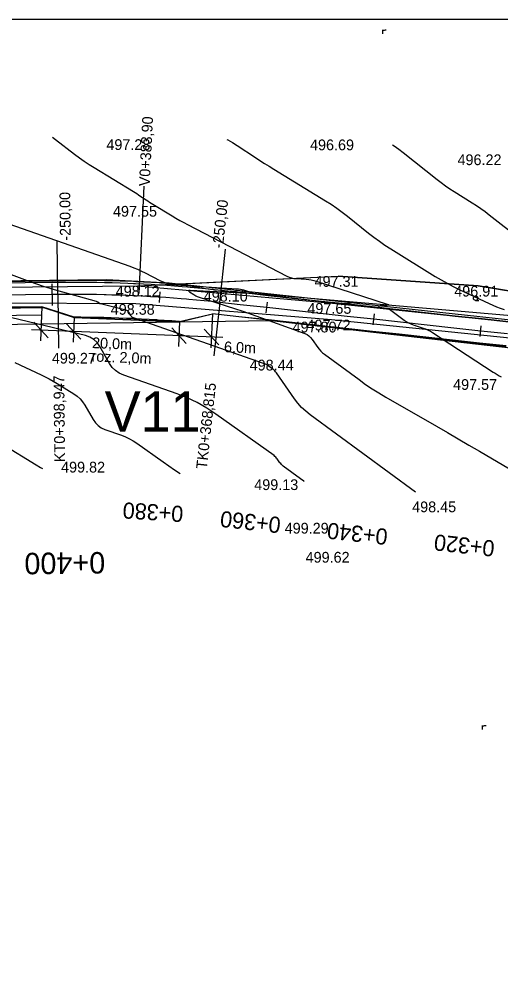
# Model space of a CAD drawing. Extents: x -636600 to -628587, y -1090963 to -1085869.
# Drawn here: x -629421.1 to -629331.5, y -1089367.8 to -1089190 of the extents above; entities that cross this region are included whole.
import ezdxf

# ---------------------------------------------------------------- set-up
doc = ezdxf.new("R2010")
doc.units = 0
for name, color, linetype in [('01_PARCELY_NÁVRH_PC', 7, 'Continuous'), ('03_PC_OBJEKTY_NÁVRH', 7, 'Continuous'), ('06_ÚSES_IP_NAVRH', 7, 'Continuous'), ('08_LEGENDA_HV', 7, 'Continuous'), ('40', 7, 'Continuous'), ('42', 7, 'Continuous'), ('43', 7, 'Continuous'), ('55', 7, 'Continuous'), ('Ex_Major Contours', 7, 'Continuous'), ('Ex_Minor Contours', 7, 'Continuous'), ('HEKTOMETRY100', 7, 'Continuous'), ('HEKTOMETRY20', 7, 'Continuous'), ('HL_BODY', 7, 'Continuous'), ('koty_vše', 7, 'Continuous'), ('POLOMERY', 7, 'Continuous'), ('popis', 7, 'Continuous'), ('situace_osa', 7, 'Continuous'), ('situace_těleso', 7, 'Continuous'), ('situace_vozovka', 7, 'Continuous'), ('VRCHOLY', 7, 'Continuous')]:
    doc.layers.add(name, color=color, linetype=linetype)

msp = doc.modelspace()

# ---------------------------------------------------------------- linework, layer by layer
at = {"layer": '01_PARCELY_NÁVRH_PC'}
for points in [[(-629219.96, -1089257.88), (-629393.2, -1089239.09), (-629404.84, -1089238.49), (-629532.17, -1089240), (-629618.76, -1089242.62), (-629630.23, -1089244.94), (-629692.43, -1089269.15), (-629702.88, -1089275.33), (-629709.57, -1089280.47), (-629719.03, -1089292.94), (-629735.64, -1089330.23), (-629741.78, -1089338.98), (-629748.13, -1089344.96), (-629754.15, -1089347.42), (-629771.79, -1089346.48), (-629796.88, -1089348.54), (-629815.64, -1089354.58), (-629845.21, -1089367.17), (-629847.27, -1089367.82)], [(-629544.07, -1089245.47), (-629416.57, -1089243.64), (-629410.87, -1089245.47), (-629391.26, -1089246.28), (-629374.19, -1089246.04), (-629308.62, -1089253.58)]]:
    msp.add_lwpolyline(points, dxfattribs=at)
for points in [[(-629393.2, -1089239.09), (-629390.9, -1089239.21), (-629361.77, -1089237.78), (-629335.73, -1089239.6), (-629294.48, -1089246.34), (-629131.6, -1089265), (-629137.99, -1089267.3), (-629219.96, -1089257.88)], [(-629391.26, -1089246.28), (-629410.87, -1089245.47), (-629416.57, -1089243.64), (-629544.07, -1089245.47), (-629606.23, -1089247.86), (-629622.77, -1089249.5), (-629631.42, -1089251.64), (-629681.41, -1089270.27), (-629685.4, -1089272.16), (-629664.77, -1089267.27), (-629630.53, -1089254.51), (-629622.26, -1089252.46), (-629606.02, -1089250.85), (-629543.99, -1089248.47), (-629417.02, -1089246.65)]]:
    msp.add_lwpolyline(points, close=True, dxfattribs=at)
at = {"layer": '06_ÚSES_IP_NAVRH'}
msp.add_lwpolyline([(-629416.96, -1089245.08), (-629541.78, -1089246.72), (-629627.12, -1089251.56), (-629664.34, -1089265.4)], dxfattribs=at)
at = {"layer": '08_LEGENDA_HV'}
msp.add_line((-629847.27, -1089189.97), (-629007.27, -1089189.97), dxfattribs=at)
at = {"layer": '40'}
for p, q in [((-629450.76, -1089240.14), (-629399.07, -1089239.61)), ((-629399.07, -1089239.61), (-629362.81, -1089242.8)), ((-629399.42, -1089242.98), (-629450.87, -1089242.7)), ((-629363.01, -1089245.9), (-629399.42, -1089242.98)), ((-629362.81, -1089242.8), (-629311.2, -1089248.31)), ((-629311.6, -1089251.23), (-629363.01, -1089245.9))]:
    msp.add_line(p, q, dxfattribs=at)
at = {"layer": '42'}
for p, q in [((-629399.07, -1089239.61), (-629361.77, -1089237.78)), ((-629335.73, -1089239.6), (-629361.77, -1089237.78)), ((-629311.31, -1089243.59), (-629335.73, -1089239.6))]:
    msp.add_line(p, q, dxfattribs=at)
at = {"layer": '43'}
for p, q in [((-629336.25, -1089242.31), (-629336.15, -1089242.31)), ((-629336.15, -1089242.31), (-629335.65, -1089242.31))]:
    msp.add_line(p, q, dxfattribs=at)
for points in [[(-629353.51, -1089192.7), (-629353.51, -1089191.97)], [(-629353.51, -1089192.21), (-629353.41, -1089192.11), (-629353.31, -1089192.05), (-629353.15, -1089192), (-629353, -1089191.98), (-629352.84, -1089191.97)], [(-629334.95, -1089322.13), (-629334.95, -1089321.4)], [(-629334.95, -1089321.63), (-629334.85, -1089321.54), (-629334.75, -1089321.47), (-629334.59, -1089321.43), (-629334.44, -1089321.4), (-629334.29, -1089321.4)]]:
    msp.add_lwpolyline(points, dxfattribs=at)
msp.add_circle((-629336.25, -1089241.91), 0.4, dxfattribs=at)
msp.add_arc((-629336.15, -1089241.91), 0.4, 259.6952, 97.1808, dxfattribs=at)
at = {"layer": '55'}
msp.add_line((-629382.61, -1089240.52), (-629320.04, -1089245.98), dxfattribs=at)
at = {"layer": 'Ex_Major Contours'}
for points in [[(-629414.92, -1089211.96), (-629414.31, -1089212.4), (-629410.79, -1089215.1), (-629409.9, -1089215.76), (-629409, -1089216.4), (-629408.08, -1089217.01), (-629407.14, -1089217.6), (-629399.83, -1089222.07), (-629399.52, -1089222.25), (-629399.22, -1089222.44), (-629398.93, -1089222.64), (-629398.63, -1089222.83), (-629397.45, -1089223.62), (-629397.15, -1089223.81), (-629396.85, -1089224), (-629396.55, -1089224.19), (-629396.25, -1089224.38), (-629392.64, -1089226.59), (-629391.94, -1089227.01), (-629391.22, -1089227.42), (-629390.5, -1089227.82), (-629389.78, -1089228.2), (-629371.35, -1089237.78), (-629370.92, -1089237.97), (-629370.49, -1089238.11), (-629370.04, -1089238.21), (-629369.58, -1089238.26), (-629367.71, -1089238.38), (-629367.25, -1089238.42), (-629366.79, -1089238.49), (-629366.33, -1089238.59), (-629365.89, -1089238.72), (-629352.68, -1089242.99), (-629352.46, -1089243.08), (-629352.39, -1089243.15), (-629352.47, -1089243.2), (-629352.71, -1089243.24), (-629353.97, -1089243.35), (-629354.2, -1089243.39), (-629354.28, -1089243.43), (-629354.21, -1089243.48), (-629353.99, -1089243.54), (-629352.8, -1089243.8), (-629352.5, -1089243.88), (-629352.23, -1089243.99), (-629351.97, -1089244.13), (-629351.72, -1089244.3), (-629349.53, -1089245.97), (-629349.13, -1089246.25), (-629348.72, -1089246.49), (-629348.28, -1089246.69), (-629347.83, -1089246.86), (-629345.98, -1089247.46), (-629345.52, -1089247.62), (-629345.08, -1089247.82), (-629344.65, -1089248.04), (-629344.24, -1089248.29), (-629332.96, -1089255.65), (-629332.6, -1089255.88), (-629332.23, -1089256.1), (-629331.86, -1089256.32), (-629331.48, -1089256.52)], [(-629424.16, -1089269.07), (-629417.92, -1089272.93), (-629417.1, -1089273.41), (-629416.76, -1089273.59)]]:
    msp.add_lwpolyline(points, dxfattribs=at)
at = {"layer": 'Ex_Minor Contours'}
for points in [[(-629382.48, -1089212.35), (-629382.29, -1089212.44), (-629381.41, -1089212.93), (-629380.55, -1089213.46), (-629377.18, -1089215.7), (-629376.33, -1089216.26), (-629375.48, -1089216.81), (-629374.63, -1089217.35), (-629373.77, -1089217.88), (-629364.15, -1089223.76), (-629363.09, -1089224.43), (-629362.05, -1089225.14), (-629361.04, -1089225.87), (-629360.04, -1089226.65), (-629356.12, -1089229.79), (-629355.13, -1089230.57), (-629354.11, -1089231.31), (-629353.08, -1089232.02), (-629352.02, -1089232.7), (-629343.75, -1089237.84), (-629342.66, -1089238.5), (-629341.55, -1089239.12), (-629340.42, -1089239.72), (-629339.28, -1089240.28), (-629333.72, -1089242.91), (-629333.04, -1089243.22), (-629332.35, -1089243.51), (-629331.65, -1089243.77), (-629330.94, -1089244.02)], [(-629351.67, -1089213.37), (-629351.36, -1089213.56), (-629350.52, -1089214.14), (-629349.7, -1089214.76), (-629343.41, -1089219.8), (-629342.64, -1089220.4), (-629341.85, -1089220.98), (-629341.05, -1089221.53), (-629340.22, -1089222.06), (-629336.9, -1089224.13), (-629336.07, -1089224.66), (-629335.26, -1089225.21), (-629334.47, -1089225.78), (-629333.69, -1089226.37), (-629327.88, -1089230.91)], [(-629428.03, -1089226.3), (-629400.51, -1089235.96), (-629399.79, -1089236.23), (-629399.07, -1089236.52), (-629398.37, -1089236.84), (-629397.67, -1089237.19), (-629394.92, -1089238.62), (-629394.22, -1089238.94), (-629393.5, -1089239.18), (-629392.75, -1089239.35), (-629391.99, -1089239.43), (-629380.61, -1089240.13), (-629380.29, -1089240.16), (-629379.97, -1089240.21), (-629379.66, -1089240.28), (-629379.36, -1089240.37), (-629377.68, -1089240.91), (-629377.62, -1089240.93), (-629377.6, -1089240.95), (-629377.63, -1089240.97), (-629377.69, -1089240.98), (-629378.03, -1089241.01), (-629378.12, -1089241.01), (-629378.21, -1089241.02), (-629378.29, -1089241.02), (-629378.38, -1089241.02), (-629389.33, -1089240.45), (-629389.52, -1089240.45), (-629389.59, -1089240.5), (-629389.56, -1089240.57), (-629389.42, -1089240.69), (-629388.64, -1089241.23), (-629388.44, -1089241.35), (-629388.23, -1089241.46), (-629388.02, -1089241.56), (-629387.8, -1089241.64), (-629380.9, -1089243.87), (-629379.68, -1089244.27), (-629378.46, -1089244.68), (-629377.25, -1089245.11), (-629376.04, -1089245.54), (-629367.99, -1089248.49), (-629367.58, -1089248.68), (-629367.22, -1089248.92), (-629366.9, -1089249.21), (-629366.61, -1089249.56), (-629365.57, -1089251.05), (-629365.3, -1089251.41), (-629365, -1089251.75), (-629364.67, -1089252.06), (-629364.32, -1089252.34), (-629357.89, -1089257.06), (-629356.69, -1089257.93), (-629355.46, -1089258.75), (-629354.21, -1089259.54), (-629352.94, -1089260.3), (-629343.48, -1089265.74), (-629341.48, -1089266.9), (-629339.48, -1089268.06), (-629337.48, -1089269.22), (-629335.49, -1089270.39), (-629318.06, -1089280.64)], [(-629347.42, -1089277.99), (-629366.99, -1089263.6), (-629367.82, -1089262.94), (-629368.58, -1089262.22), (-629369.28, -1089261.44), (-629369.91, -1089260.6), (-629373.27, -1089255.78), (-629373.42, -1089255.59), (-629373.58, -1089255.4), (-629373.76, -1089255.24), (-629373.96, -1089255.08), (-629374.77, -1089254.5), (-629374.98, -1089254.37), (-629375.19, -1089254.25), (-629375.42, -1089254.14), (-629375.65, -1089254.05), (-629399.85, -1089245.54), (-629400.01, -1089245.47), (-629400.14, -1089245.38), (-629400.26, -1089245.26), (-629400.36, -1089245.12), (-629400.71, -1089244.5), (-629400.81, -1089244.37), (-629400.93, -1089244.25), (-629401.07, -1089244.17), (-629401.23, -1089244.12), (-629405.99, -1089242.97), (-629406.05, -1089242.95), (-629406.12, -1089242.93), (-629406.18, -1089242.89), (-629406.24, -1089242.85), (-629406.47, -1089242.67), (-629406.52, -1089242.63), (-629406.59, -1089242.59), (-629406.65, -1089242.56), (-629406.72, -1089242.54), (-629414.1, -1089240.49), (-629415.35, -1089240.12), (-629416.59, -1089239.73), (-629417.82, -1089239.32), (-629419.04, -1089238.87), (-629436.12, -1089232.46)], [(-629368.1, -1089276), (-629368.18, -1089275.94), (-629368.78, -1089275.51), (-629372, -1089273.14), (-629372.17, -1089273), (-629372.33, -1089272.85), (-629372.47, -1089272.69), (-629372.6, -1089272.52), (-629373.1, -1089271.81), (-629373.23, -1089271.64), (-629373.37, -1089271.48), (-629373.53, -1089271.33), (-629373.7, -1089271.2), (-629384.5, -1089263.47), (-629386.21, -1089262.34), (-629387.98, -1089261.34), (-629389.83, -1089260.46), (-629391.73, -1089259.72), (-629401.66, -1089256.23), (-629402.47, -1089255.86), (-629403.18, -1089255.38), (-629403.79, -1089254.77), (-629404.29, -1089254.04), (-629406.1, -1089250.87), (-629406.61, -1089250.15), (-629407.22, -1089249.57), (-629407.95, -1089249.14), (-629408.78, -1089248.86), (-629433.36, -1089242.96)], [(-629421.9, -1089253.84), (-629417.03, -1089256.14), (-629416.26, -1089256.51), (-629415.5, -1089256.91), (-629414.75, -1089257.33), (-629414.02, -1089257.77), (-629410.94, -1089259.67), (-629410.32, -1089260.11), (-629409.77, -1089260.61), (-629409.29, -1089261.18), (-629408.87, -1089261.81), (-629407.35, -1089264.48), (-629406.92, -1089265.1), (-629406.41, -1089265.61), (-629405.82, -1089266.02), (-629405.14, -1089266.33), (-629402.04, -1089267.41), (-629401.3, -1089267.71), (-629400.58, -1089268.05), (-629399.88, -1089268.44), (-629399.22, -1089268.88), (-629394.33, -1089272.37), (-629393.29, -1089273.1), (-629392.24, -1089273.81), (-629391.18, -1089274.5), (-629391.17, -1089274.51)]]:
    msp.add_lwpolyline(points, dxfattribs=at)
at = {"layer": 'HEKTOMETRY100'}
msp.add_lwpolyline([(-629414.92, -1089243.23), (-629414.97, -1089239.23)], dxfattribs=at)
at = {"layer": 'HEKTOMETRY20'}
for points in [[(-629395.02, -1089242.72), (-629394.89, -1089240.72)], [(-629375.16, -1089244.65), (-629374.94, -1089242.66)], [(-629355.28, -1089246.83), (-629355.06, -1089244.84)], [(-629335.4, -1089249), (-629335.18, -1089247.02)]]:
    msp.add_lwpolyline(points, dxfattribs=at)
at = {"layer": 'HL_BODY'}
for points in [[(-629413.89, -1089241.22), (-629413.78, -1089251.22)], [(-629383.81, -1089242.69), (-629384.9, -1089252.63)]]:
    msp.add_lwpolyline(points, dxfattribs=at)
at = {"layer": 'POLOMERY'}
for points in [[(-629413.89, -1089241.22), (-629414, -1089231.22)], [(-629383.81, -1089242.69), (-629382.72, -1089232.75)]]:
    msp.add_lwpolyline(points, dxfattribs=at)
at = {"layer": 'popis'}
for points in [[(-629416.86, -1089243.5), (-629417.12, -1089249.83)], [(-629410.87, -1089245.45), (-629411.06, -1089250.07)], [(-629385.17, -1089244.81), (-629385.43, -1089251.12)], [(-629418.39, -1089246.36), (-629415.68, -1089249.3)], [(-629412.33, -1089246.6), (-629409.62, -1089249.55)], [(-629391.26, -1089246.25), (-629391.45, -1089250.87)], [(-629383.21, -1089249.21), (-629418.78, -1089247.76)], [(-629392.73, -1089247.41), (-629390.02, -1089250.35)], [(-629386.7, -1089247.65), (-629383.99, -1089250.59)]]:
    msp.add_lwpolyline(points, dxfattribs=at)
at = {"layer": 'situace_osa'}
msp.add_lwpolyline([(-629330.32, -1089248.56), (-629335.29, -1089248.01), (-629340.26, -1089247.47), (-629345.23, -1089246.92), (-629350.2, -1089246.38), (-629355.17, -1089245.83), (-629360.14, -1089245.29), (-629365.11, -1089244.74), (-629370.08, -1089244.2), (-629375.05, -1089243.65), (-629380.02, -1089243.11), (-629383.81, -1089242.69), (-629384.99, -1089242.56), (-629385.24, -1089242.54), (-629386.67, -1089242.39), (-629388.1, -1089242.26), (-629389.52, -1089242.13), (-629389.97, -1089242.09), (-629390.95, -1089242.01), (-629392.38, -1089241.9), (-629393.82, -1089241.8), (-629394.95, -1089241.72), (-629395.25, -1089241.7), (-629396.68, -1089241.62), (-629398.11, -1089241.54), (-629399.55, -1089241.47), (-629399.95, -1089241.45), (-629400.98, -1089241.41), (-629402.41, -1089241.35), (-629403.85, -1089241.31), (-629404.94, -1089241.28), (-629405.28, -1089241.27), (-629406.72, -1089241.24), (-629408.15, -1089241.22), (-629409.59, -1089241.21), (-629409.94, -1089241.2), (-629411.02, -1089241.2), (-629412.46, -1089241.21), (-629413.89, -1089241.22), (-629414.94, -1089241.23), (-629419.94, -1089241.29), (-629424.94, -1089241.34)], dxfattribs=at)
at = {"layer": 'situace_těleso'}
for p, q in [((-629410.87, -1089245.47), (-629416.85, -1089243.56)), ((-629391.26, -1089246.28), (-629385.17, -1089244.84))]:
    msp.add_line(p, q, dxfattribs=at)
for points in [[(-629424.97, -1089238.87), (-629419.97, -1089238.75), (-629414.97, -1089238.64), (-629413.92, -1089238.62), (-629412.47, -1089238.59), (-629411.02, -1089238.57), (-629409.93, -1089238.56), (-629409.57, -1089238.56), (-629408.12, -1089238.56), (-629406.67, -1089238.56), (-629405.22, -1089238.58), (-629404.88, -1089238.59), (-629403.77, -1089238.61), (-629402.32, -1089238.64), (-629400.87, -1089238.7), (-629399.83, -1089238.75), (-629399.42, -1089238.77), (-629397.97, -1089238.84), (-629396.52, -1089238.92), (-629395.08, -1089239), (-629394.78, -1089239.02), (-629393.63, -1089239.1), (-629392.18, -1089239.2), (-629390.74, -1089239.37), (-629389.75, -1089239.52), (-629389.3, -1089239.59), (-629387.87, -1089239.82), (-629386.44, -1089240.07), (-629385.01, -1089240.29), (-629384.75, -1089240.31), (-629383.56, -1089240.39), (-629379.76, -1089240.77), (-629374.8, -1089241.38), (-629369.83, -1089241.94), (-629364.86, -1089242.44), (-629359.88, -1089242.94), (-629354.91, -1089243.48), (-629349.94, -1089244.06), (-629344.98, -1089244.64), (-629340.01, -1089245.23), (-629335.04, -1089245.75), (-629330.07, -1089246.27)], [(-629416.85, -1089243.56), (-629419.92, -1089243.61), (-629424.92, -1089243.7), (-629429.91, -1089243.78), (-629434.91, -1089243.87), (-629439.91, -1089243.96), (-629444.91, -1089244.05), (-629449.91, -1089244.08), (-629454.91, -1089244.15), (-629459.91, -1089244.21), (-629464.91, -1089244.28), (-629469.91, -1089244.35), (-629474.91, -1089244.44), (-629479.91, -1089244.53), (-629484.91, -1089244.61), (-629489.91, -1089244.66), (-629494.91, -1089244.68), (-629499.91, -1089244.71), (-629504.91, -1089244.75), (-629509.91, -1089244.79), (-629514.91, -1089244.83), (-629519.91, -1089244.87), (-629524.91, -1089244.91)], [(-629391.26, -1089246.28), (-629392.71, -1089246.17), (-629394.12, -1089246.06), (-629395.24, -1089245.98), (-629395.52, -1089245.96), (-629396.93, -1089245.87), (-629398.32, -1089245.8), (-629399.78, -1089245.73), (-629400.16, -1089245.7), (-629401.14, -1089245.67), (-629402.57, -1089245.62), (-629403.97, -1089245.57), (-629405.05, -1089245.54), (-629405.38, -1089245.53), (-629406.79, -1089245.5), (-629408.2, -1089245.48), (-629409.61, -1089245.47), (-629409.95, -1089245.47), (-629410.87, -1089245.47)], [(-629330.58, -1089250.96), (-629335.55, -1089250.37), (-629340.51, -1089249.78), (-629345.48, -1089249.19), (-629350.45, -1089248.63), (-629355.42, -1089248.13), (-629360.39, -1089247.61), (-629365.36, -1089247), (-629370.33, -1089246.46), (-629375.3, -1089245.92), (-629380.27, -1089245.38), (-629384.06, -1089244.96), (-629385.17, -1089244.84)]]:
    msp.add_lwpolyline(points, dxfattribs=at)
at = {"layer": 'situace_vozovka'}
for p, q in [((-629410.87, -1089245.45), (-629416.86, -1089243.5)), ((-629391.26, -1089246.25), (-629385.17, -1089244.81))]:
    msp.add_line(p, q, dxfattribs=at)
for points in [[(-629330.07, -1089246.32), (-629335.04, -1089245.77), (-629340.01, -1089245.23), (-629344.98, -1089244.68), (-629349.95, -1089244.14), (-629354.92, -1089243.59), (-629359.89, -1089243.05), (-629364.86, -1089242.5), (-629369.83, -1089241.96), (-629374.8, -1089241.42), (-629379.77, -1089240.87), (-629383.57, -1089240.45), (-629384.76, -1089240.33), (-629385.01, -1089240.3), (-629386.45, -1089240.16), (-629387.89, -1089240.02), (-629389.33, -1089239.89), (-629389.78, -1089239.85), (-629390.77, -1089239.77), (-629392.22, -1089239.66), (-629393.66, -1089239.55), (-629394.81, -1089239.48), (-629395.11, -1089239.46), (-629396.55, -1089239.37), (-629398, -1089239.29), (-629399.44, -1089239.22), (-629399.85, -1089239.2), (-629400.89, -1089239.16), (-629402.34, -1089239.1), (-629403.78, -1089239.06), (-629404.89, -1089239.03), (-629405.23, -1089239.02), (-629406.68, -1089238.99), (-629408.12, -1089238.97), (-629409.57, -1089238.96), (-629409.93, -1089238.95), (-629411.02, -1089238.95), (-629412.47, -1089238.96), (-629413.92, -1089238.97), (-629414.97, -1089238.98), (-629419.97, -1089239.04), (-629424.97, -1089239.09)], [(-629416.86, -1089243.5), (-629419.92, -1089243.54), (-629424.92, -1089243.59), (-629429.92, -1089243.65), (-629434.92, -1089243.71), (-629439.92, -1089243.76), (-629444.92, -1089243.82), (-629449.92, -1089243.88), (-629454.91, -1089243.93), (-629459.91, -1089243.99), (-629464.91, -1089244.05), (-629469.91, -1089244.1), (-629474.91, -1089244.16), (-629479.91, -1089244.22), (-629484.91, -1089244.27), (-629489.91, -1089244.33), (-629494.91, -1089244.39), (-629499.91, -1089244.44), (-629504.91, -1089244.5), (-629509.91, -1089244.56), (-629514.91, -1089244.61), (-629519.91, -1089244.67), (-629524.91, -1089244.73)], [(-629391.26, -1089246.25), (-629391.3, -1089246.25), (-629392.7, -1089246.14), (-629394.11, -1089246.04), (-629395.23, -1089245.96), (-629395.51, -1089245.94), (-629396.92, -1089245.86), (-629398.33, -1089245.78), (-629399.74, -1089245.71), (-629400.13, -1089245.7), (-629401.15, -1089245.65), (-629402.56, -1089245.6), (-629403.97, -1089245.55), (-629405.05, -1089245.53), (-629405.38, -1089245.52), (-629406.79, -1089245.49), (-629408.2, -1089245.47), (-629409.61, -1089245.46), (-629409.96, -1089245.45), (-629410.87, -1089245.45)], [(-629330.56, -1089250.79), (-629335.53, -1089250.25), (-629340.5, -1089249.7), (-629345.47, -1089249.16), (-629350.44, -1089248.61), (-629355.41, -1089248.07), (-629360.38, -1089247.52), (-629365.35, -1089246.98), (-629370.32, -1089246.43), (-629375.29, -1089245.89), (-629380.27, -1089245.34), (-629384.06, -1089244.93), (-629385.17, -1089244.81)]]:
    msp.add_lwpolyline(points, dxfattribs=at)
at = {"layer": 'VRCHOLY'}
msp.add_lwpolyline([(-629398.81, -1089241.05), (-629397.83, -1089221.07)], dxfattribs=at)

# ---------------------------------------------------------------- texts
at = {"layer": '03_PC_OBJEKTY_NÁVRH'}
msp.add_text('V11', height=7.5, dxfattribs=at).set_placement((-629405.2, -1089266.74))
at = {"layer": 'HEKTOMETRY100'}
msp.add_text('0+400', height=4, rotation=180.6497, dxfattribs=at).set_placement((-629405.12, -1089289.12))
at = {"layer": 'HEKTOMETRY20'}
for s, rotation, p in [('0+380', 176.3074, (-629390.49, -1089280.59)), ('0+360', 173.7441, (-629372.33, -1089282.68)), ('0+340', 173.7441, (-629352.45, -1089284.86)), ('0+320', 173.7441, (-629332.57, -1089287.04))]:
    msp.add_text(s, height=3, rotation=rotation, dxfattribs=at).set_placement(p)
at = {"layer": 'HL_BODY'}
for s, rotation, p in [('KT0+398,947', 90.6497, (-629412.54, -1089272.39)), ('TK0+368,815', 83.7441, (-629386.22, -1089273.79))]:
    msp.add_text(s, height=2, rotation=rotation, dxfattribs=at).set_placement(p)
at = {"layer": 'koty_vše'}
for s, p in [('497.28', (-629404.88, -1089214.32)), ('496.69', (-629367.02, -1089214.37)), ('496.22', (-629339.6, -1089217.14)), ('497.55', (-629403.65, -1089226.73)), ('497.31', (-629366.18, -1089239.78)), ('498.12', (-629403.15, -1089241.61)), ('496.91', (-629340.21, -1089241.6)), ('498.10', (-629386.78, -1089242.52)), ('498.38', (-629404.07, -1089244.98)), ('497.65', (-629367.51, -1089244.8)), ('497.80', (-629370.27, -1089248.27)), ('497.72', (-629367.66, -1089247.9)), ('499.27', (-629415.01, -1089254.07)), ('498.44', (-629378.24, -1089255.35)), ('497.57', (-629340.42, -1089258.96)), ('499.82', (-629413.3, -1089274.34)), ('499.13', (-629377.39, -1089277.6)), ('498.45', (-629348.03, -1089281.73)), ('499.29', (-629371.73, -1089285.7)), ('499.62', (-629367.84, -1089291.11))]:
    msp.add_text(s, height=2, dxfattribs=at).set_placement(p)
at = {"layer": 'POLOMERY'}
for rotation, p in [(90.6497, (-629411.5, -1089231.19)), (83.7441, (-629383.22, -1089232.7))]:
    msp.add_text('-250,00', height=2, rotation=rotation, dxfattribs=at).set_placement(p)
at = {"layer": 'popis'}
for s, p in [('20,0m', (-629407.57, -1089251.18)), ('6,0m', (-629383.04, -1089251.94)), ('roz. 2,0m', (-629407.67, -1089253.67))]:
    msp.add_text(s, height=2, rotation=357.6619, dxfattribs=at).set_placement(p)
at = {"layer": 'VRCHOLY'}
msp.add_text('V0+383,90', height=2, rotation=87.1969, dxfattribs=at).set_placement((-629396.83, -1089221.12))

doc.saveas('drawing.dxf')
